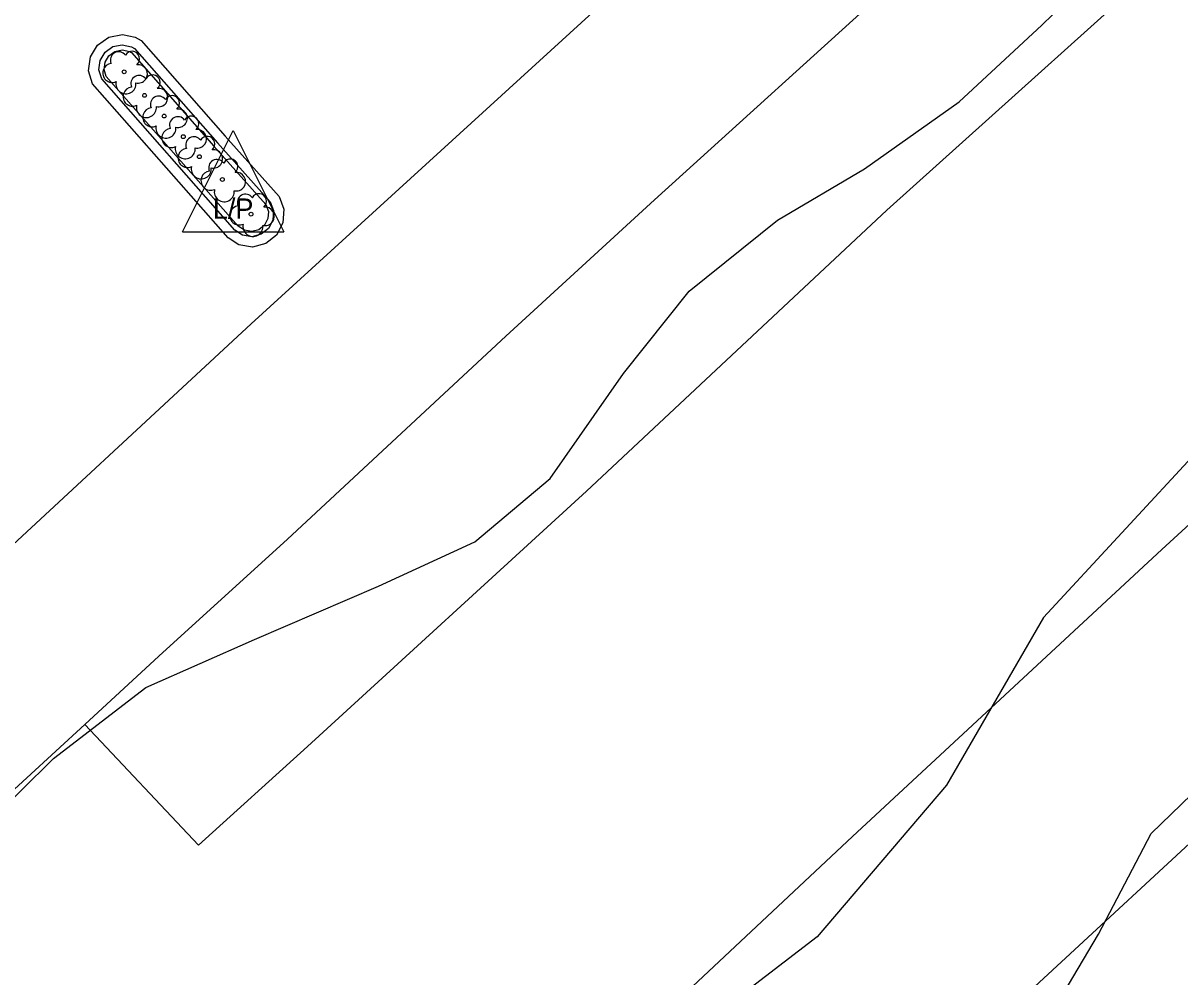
# Model space of a CAD drawing. Extents: x 2161152 to 2175754, y 602179 to 617749.
# Drawn here: x 2164507.6 to 2164621.8, y 606987.4 to 607081.5 of the extents above; entities that cross this region are included whole.
import ezdxf

# ---------------------------------------------------------------- set-up
doc = ezdxf.new("R2010")
doc.units = 0
for name, color, linetype in [('RD_EX_Conc_Curb', 7, 'Continuous'), ('RD_EX_Conc_Gutter', 7, 'Continuous'), ('RD_EX_Parking_Conc', 7, 'Continuous'), ('RD_EX_Road', 7, 'Continuous'), ('RD_EX_UT', 7, 'Continuous'), ('RD_EX_VEG', 7, 'Continuous')]:
    doc.layers.add(name, color=color, linetype=linetype)

msp = doc.modelspace()

# ---------------------------------------------------------------- linework, layer by layer
at = {"layer": 'RD_EX_Conc_Curb'}
for points in [[(2164526.83, 607069.68), (2164532.02, 607063.88), (2164532.35, 607063.01), (2164532.29, 607062.07), (2164531.86, 607061.25), (2164531.13, 607060.67), (2164530.22, 607060.43), (2164529.3, 607060.59), (2164528.54, 607061.09), (2164515.39, 607075.99), (2164515.12, 607076.9), (2164515.24, 607077.83), (2164515.72, 607078.64), (2164516.49, 607079.18), (2164517.42, 607079.37), (2164518.34, 607079.17), (2164518.64, 607079), (2164526.83, 607069.68)], [(2164526.46, 607069.35), (2164531.58, 607063.62), (2164531.84, 607062.93), (2164531.8, 607062.21), (2164531.47, 607061.57), (2164530.9, 607061.12), (2164530.2, 607060.94), (2164529.49, 607061.06), (2164528.87, 607061.48), (2164515.83, 607076.24), (2164515.63, 607076.94), (2164515.72, 607077.66), (2164516.1, 607078.29), (2164516.69, 607078.71), (2164517.41, 607078.86), (2164518.16, 607078.69), (2164518.32, 607078.6), (2164526.46, 607069.35)]]:
    msp.add_lwpolyline(points, dxfattribs=at)
at = {"layer": 'RD_EX_Conc_Gutter'}
msp.add_lwpolyline([(2164527.58, 607070.34), (2164532.89, 607064.41), (2164533.36, 607063.16), (2164533.28, 607061.8), (2164532.65, 607060.59), (2164531.58, 607059.75), (2164530.27, 607059.41), (2164528.93, 607059.64), (2164527.88, 607060.33), (2164514.49, 607075.5), (2164514.1, 607076.81), (2164514.27, 607078.17), (2164514.97, 607079.34), (2164516.09, 607080.12), (2164517.43, 607080.39), (2164518.69, 607080.11), (2164519.28, 607079.79), (2164527.58, 607070.34)], dxfattribs=at)
at = {"layer": 'RD_EX_Parking_Conc'}
for points in [[(2164812.05, 607285.6), (2164823.91, 607278.73), (2164804.57, 607260.67), (2164782.4, 607239.65), (2164759.11, 607216.82), (2164739.06, 607197.58), (2164721.62, 607181.26), (2164698.79, 607159.63), (2164665.32, 607128.18), (2164625.66, 607092.56), (2164592.87, 607063.04), (2164563.24, 607035.31), (2164535.69, 607010.12), (2164524.95, 607000.4), (2164513.73, 607012.32)], [(2164500.72, 607024.61), (2164530.13, 607051.83), (2164567.57, 607086.01), (2164604.7, 607120.03), (2164635.22, 607147.89), (2164668.43, 607178.25), (2164698.17, 607205.51), (2164720.63, 607226.05), (2164752.14, 607254.86)], [(2164752.91, 607231.58), (2164730.26, 607210.68), (2164698.49, 607181.57), (2164669.19, 607154.89), (2164644.82, 607132.6), (2164619.79, 607109.42), (2164594.06, 607085.95), (2164569.96, 607064.07), (2164555.28, 607050.63), (2164533.71, 607030.59), (2164521.04, 607019.03), (2164513.73, 607012.32), (2164499.39, 606999.15)]]:
    msp.add_lwpolyline(points, dxfattribs=at)
at = {"layer": 'RD_EX_Road'}
for points in [[(2164897.24, 607284.78), (2164866.3, 607256.24), (2164854.34, 607245.14), (2164840.72, 607232.6), (2164811.12, 607205.24), (2164771.37, 607168.66), (2164739.75, 607139.56), (2164697.58, 607100.8), (2164659.67, 607065.9), (2164620.03, 607029.56), (2164589.5, 607001.24), (2164551.11, 606965.27)], [(2164600.48, 606979.99), (2164633.27, 607010.3), (2164675.44, 607049.12), (2164716.51, 607086.96), (2164760.55, 607126.83), (2164793.55, 607157.33), (2164831.07, 607191.66), (2164853.4, 607211.86), (2164861.77, 607219.5), (2164870.28, 607226.34), (2164884.3, 607238.67)]]:
    msp.add_lwpolyline(points, dxfattribs=at)
at = {"layer": 'RD_EX_UT'}
for p, q in [((2164523.36, 607060.92), (2164528.36, 607070.92)), ((2164528.36, 607070.92), (2164533.36, 607060.92)), ((2164523.36, 607060.92), (2164533.36, 607060.92))]:
    msp.add_line(p, q, dxfattribs=at)
at = {"layer": 'RD_EX_VEG'}
for points in [[(2164889, 607282.05), (2164866.13, 607261.39), (2164839.58, 607236.56), (2164823.57, 607217.96), (2164804.38, 607199.85), (2164794.28, 607191.51), (2164774.23, 607176.09), (2164761.22, 607163.4), (2164748.23, 607148.66), (2164733.74, 607135.87), (2164721.99, 607121.22), (2164709.2, 607107.7), (2164695.1, 607093.5), (2164679.42, 607080.22), (2164663.92, 607070.14), (2164635.23, 607049.12), (2164623.81, 607039.58), (2164608.33, 607022.86), (2164598.75, 607006.33), (2164585.99, 606991.35), (2164571.14, 606979.94)], [(2164604.8, 606976.47), (2164613.78, 606991.63), (2164618.95, 607001.54), (2164631.87, 607014.01), (2164647.09, 607023.38), (2164659.96, 607031.28), (2164674.32, 607038.83), (2164685.35, 607045.65), (2164694.35, 607054.45), (2164704.67, 607066.99), (2164717.48, 607079.72), (2164731.74, 607093.77), (2164750.53, 607110.49), (2164765.72, 607123.69)], [(2164504.1, 607002.49), (2164510.62, 607008.96), (2164519.73, 607015.94), (2164530.48, 607020.7), (2164542.72, 607025.96), (2164552.22, 607030.31), (2164559.66, 607036.59), (2164566.88, 607046.93), (2164573.37, 607055.06), (2164582.07, 607062.07), (2164590.68, 607067.14), (2164600.01, 607073.72), (2164608.19, 607081.3), (2164614.7, 607087.66), (2164624.96, 607098.66)]]:
    msp.add_lwpolyline(points, dxfattribs=at)
for centre in [(2164517.6, 607076.7), (2164519.62, 607074.37), (2164521.55, 607072.33), (2164523.44, 607070.3), (2164525.03, 607068.32), (2164527.3, 607066.07), (2164530.13, 607062.65)]:
    msp.add_circle(centre, 0.188, dxfattribs=at)
for centre, radius, start, end in [((2164517.06, 607077.86), 0.813, 34.9763, 204.756), ((2164518.38, 607077.98), 0.746, 308.7626, 152.0467), ((2164516.43, 607076.59), 0.943, 96.4518, 294.734), ((2164518.98, 607076.49), 0.914, 256.5667, 98.1046), ((2164517.78, 607075.51), 0.988, 166.8827, 5.7589), ((2164519.08, 607075.53), 0.813, 34.9763, 204.756), ((2164520.4, 607075.65), 0.746, 308.7626, 152.0467), ((2164518.44, 607074.25), 0.943, 96.4518, 294.734), ((2164521, 607074.16), 0.914, 256.5667, 98.1046), ((2164522.33, 607073.61), 0.746, 308.7626, 152.0467), ((2164519.8, 607073.17), 0.988, 166.8827, 5.7589), ((2164521.01, 607073.49), 0.813, 34.9763, 204.756), ((2164520.38, 607072.22), 0.943, 96.4518, 294.734), ((2164522.9, 607071.46), 0.813, 34.9763, 204.756), ((2164522.93, 607072.12), 0.914, 256.5667, 98.1046), ((2164524.23, 607071.58), 0.746, 308.7626, 152.0467), ((2164521.73, 607071.14), 0.988, 166.8827, 5.7589), ((2164522.27, 607070.18), 0.943, 96.4518, 294.734), ((2164524.82, 607070.09), 0.914, 256.5667, 98.1046), ((2164524.49, 607069.48), 0.813, 34.9763, 204.756), ((2164525.81, 607069.59), 0.746, 308.7626, 152.0467), ((2164523.63, 607069.1), 0.988, 166.8827, 5.7589), ((2164523.86, 607068.2), 0.943, 96.4518, 294.734), ((2164526.41, 607068.11), 0.914, 256.5667, 98.1046), ((2164526.76, 607067.23), 0.813, 34.9763, 204.756), ((2164528.09, 607067.35), 0.746, 308.7626, 152.0467), ((2164525.21, 607067.12), 0.988, 166.8827, 5.7589), ((2164526.13, 607065.96), 0.943, 96.4518, 294.734), ((2164528.68, 607065.86), 0.914, 256.5667, 98.1046), ((2164527.49, 607064.87), 0.988, 166.8827, 5.7589), ((2164529.59, 607063.81), 0.813, 34.9763, 204.756), ((2164530.91, 607063.93), 0.746, 308.7626, 152.0467), ((2164528.96, 607062.53), 0.943, 96.4518, 294.734), ((2164531.51, 607062.44), 0.914, 256.5667, 98.1046), ((2164530.31, 607061.45), 0.988, 166.8827, 5.7589)]:
    msp.add_arc(centre, radius, start, end, dxfattribs=at)

# ---------------------------------------------------------------- texts
at = {"layer": 'RD_EX_UT'}
msp.add_text('L/P', height=2, dxfattribs=at).set_placement((2164526.35, 607062.2))

doc.saveas('drawing.dxf')
